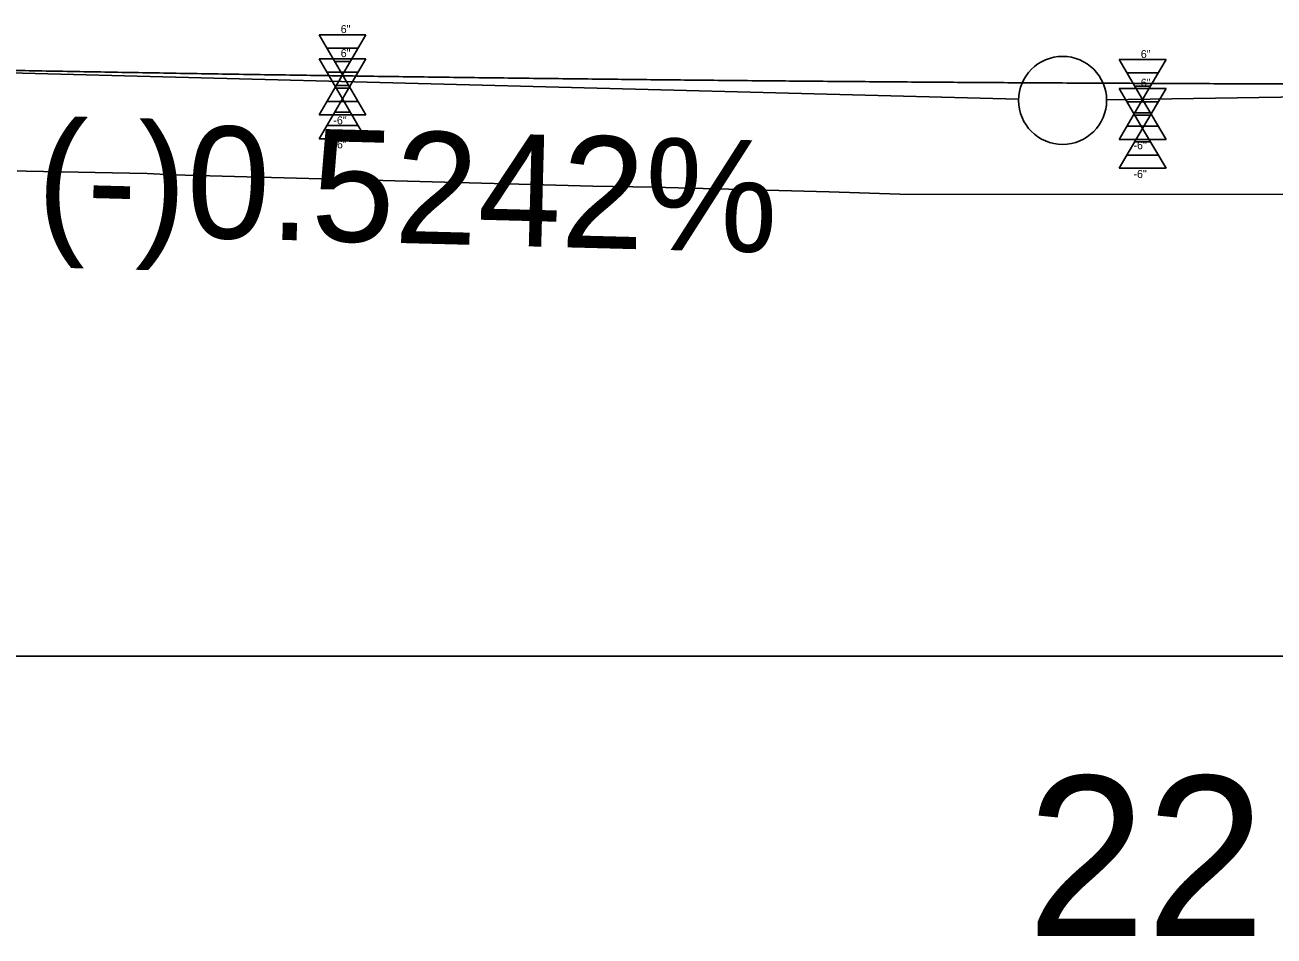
# Model space of a CAD drawing. Extents: x 573468 to 580768, y -57414 to -51768.
# Drawn here: x 574895.4 to 574973.4, y -53116 to -53059.1 of the extents above; entities that cross this region are included whole.
import ezdxf

# ---------------------------------------------------------------- set-up
doc = ezdxf.new("R2010")
doc.units = 0
for name, color, linetype in [('Exist Profile Cell', 7, 'Continuous'), ('Exist Vertical Profile Ground Line', 7, 'Continuous'), ('Exist Vertical Profile Horizontal Axis Label Major', 7, 'Continuous'), ('Pattern 2', 7, 'Continuous'), ('Prop Vertical Profile Grade', 7, 'Continuous'), ('Prop Vertical Profile Grade Label', 7, 'Continuous'), ('Prop VPI Label', 7, 'Continuous'), ('Scratch_Level_0', 7, 'Continuous')]:
    doc.layers.add(name, color=color, linetype=linetype)

msp = doc.modelspace()

# ---------------------------------------------------------------- linework, layer by layer
at = {"layer": 'Exist Profile Cell'}
msp.add_line((573765.214, -53098.544), (577467.911, -53098.544), dxfattribs=at)
at = {"layer": 'Exist Vertical Profile Ground Line'}
msp.add_lwpolyline([(574894.873, -53068.196), (574895.453, -53068.226), (574903.013, -53068.368), (574904.614, -53068.443), (574930.856, -53069.158), (574934.597, -53069.217), (574945.634, -53069.511), (574950.046, -53069.666), (574974.556, -53069.672)], dxfattribs=at)
at = {"layer": 'Pattern 2'}
for p, q in [((574913.748, -53061.194), (574916.68, -53061.194)), ((574913.748, -53061.194), (574915.214, -53063.694)), ((574915.214, -53063.694), (574916.68, -53061.194)), ((574914.236, -53062.028), (574916.191, -53062.028)), ((574914.725, -53062.861), (574915.703, -53062.861)), ((574913.748, -53066.194), (574915.214, -53063.694)), ((574915.214, -53063.694), (574916.68, -53066.194)), ((574963.748, -53063.044), (574966.68, -53063.044)), ((574963.748, -53063.044), (574965.214, -53065.544)), ((574965.214, -53065.544), (574966.68, -53063.044)), ((574914.725, -53064.528), (574915.703, -53064.528)), ((574964.236, -53063.878), (574966.191, -53063.878)), ((574964.725, -53064.711), (574965.703, -53064.711)), ((574914.236, -53065.361), (574916.191, -53065.361)), ((574963.748, -53068.044), (574965.214, -53065.544)), ((574965.214, -53065.544), (574966.68, -53068.044)), ((574913.748, -53066.194), (574916.68, -53066.194)), ((574964.725, -53066.378), (574965.703, -53066.378)), ((574964.236, -53067.211), (574966.191, -53067.211)), ((574963.748, -53068.044), (574966.68, -53068.044))]:
    msp.add_line(p, q, dxfattribs=at)
at = {"layer": 'Prop Vertical Profile Grade'}
msp.add_spline([(574855.214, -53061.042), (574859.414, -53061.151), (574863.614, -53061.256), (574867.814, -53061.357), (574872.014, -53061.455), (574876.214, -53061.549), (574880.414, -53061.64), (574884.614, -53061.728), (574888.814, -53061.812), (574893.014, -53061.892), (574897.214, -53061.969), (574901.414, -53062.043), (574905.614, -53062.113), (574909.814, -53062.18), (574914.014, -53062.243), (574918.214, -53062.303), (574922.414, -53062.359), (574926.614, -53062.411), (574930.814, -53062.461), (574935.014, -53062.506), (574939.214, -53062.549), (574943.414, -53062.588), (574947.614, -53062.623), (574951.814, -53062.655), (574956.014, -53062.683), (574960.214, -53062.708), (574964.414, -53062.729), (574968.614, -53062.747), (574972.814, -53062.762), (574977.014, -53062.773), (574981.214, -53062.78), (574985.414, -53062.784), (574989.614, -53062.785), (574993.814, -53062.782), (574998.014, -53062.776), (575002.214, -53062.766), (575006.414, -53062.753), (575010.614, -53062.736), (575014.814, -53062.715), (575019.014, -53062.692), (575023.214, -53062.664), (575027.414, -53062.634), (575031.614, -53062.599), (575035.814, -53062.562), (575040.014, -53062.521), (575044.214, -53062.476), (575048.414, -53062.428), (575052.614, -53062.376), (575056.814, -53062.321), (575061.014, -53062.263), (575065.214, -53062.201)], degree=3, dxfattribs=at)
at = {"layer": 'Prop VPI Label'}
for p, q in [((574855.214, -53061.042), (574957.465, -53063.722)), ((575065.214, -53062.201), (574962.964, -53063.753))]:
    msp.add_line(p, q, dxfattribs=at)
msp.add_circle((574960.214, -53063.795), 2.75, dxfattribs=at)
at = {"layer": 'Scratch_Level_0'}
for p, q in [((574913.748, -53059.689), (574916.68, -53059.689)), ((574913.748, -53059.689), (574915.214, -53062.189)), ((574915.214, -53062.189), (574916.68, -53059.689)), ((574914.236, -53060.523), (574916.191, -53060.523)), ((574914.725, -53061.356), (574915.703, -53061.356)), ((574963.748, -53061.249), (574966.68, -53061.249)), ((574963.748, -53061.249), (574965.214, -53063.749)), ((574965.214, -53063.749), (574966.68, -53061.249)), ((574913.748, -53064.689), (574915.214, -53062.189)), ((574915.214, -53062.189), (574916.68, -53064.689)), ((574964.236, -53062.083), (574966.191, -53062.083)), ((574964.725, -53062.916), (574965.703, -53062.916)), ((574914.725, -53063.023), (574915.703, -53063.023)), ((574963.748, -53066.249), (574965.214, -53063.749)), ((574965.214, -53063.749), (574966.68, -53066.249)), ((574914.236, -53063.856), (574916.191, -53063.856)), ((574913.748, -53064.689), (574916.68, -53064.689)), ((574964.725, -53064.583), (574965.703, -53064.583)), ((574964.236, -53065.416), (574966.191, -53065.416)), ((574963.748, -53066.249), (574966.68, -53066.249))]:
    msp.add_line(p, q, dxfattribs=at)

# ---------------------------------------------------------------- texts
at = {"layer": 'Exist Vertical Profile Horizontal Axis Label Major'}
msp.add_text('22', height=10, dxfattribs=at).set_placement((574957.988, -53116.044))
at = {"layer": 'Pattern 2'}
for s, p in [('6"', (574915.101, -53061.093)), ('6"', (574965.101, -53062.943)), ('-6"', (574914.64, -53066.797)), ('-6"', (574964.64, -53068.647))]:
    msp.add_text(s, height=0.5, rotation=360, dxfattribs=at).set_placement(p)
at = {"layer": 'Prop Vertical Profile Grade Label'}
msp.add_text('(-)0.5242%', height=7, rotation=358.49864, dxfattribs=at).set_placement((574896.046, -53072.116))
at = {"layer": 'Scratch_Level_0'}
for s, p in [('6"', (574915.101, -53059.588)), ('6"', (574965.101, -53061.148)), ('-6"', (574914.64, -53065.292)), ('-6"', (574964.64, -53066.852))]:
    msp.add_text(s, height=0.5, dxfattribs=at).set_placement(p)

doc.saveas('drawing.dxf')
